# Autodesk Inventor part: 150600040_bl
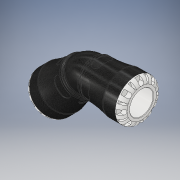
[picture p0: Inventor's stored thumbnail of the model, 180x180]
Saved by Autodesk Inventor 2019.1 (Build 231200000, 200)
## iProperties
Created: 2016-12
Part Number: 150600040_bl
Material: PVC-Piping
Description: PLASSON G-PLASS 45°  ELBOW 40-40
Document SubType Name: Modeling
Designer: KIM
Mass: 664.223 g
Surface Area: 733.008 cm^2
Volume: 474.445 cm^3
Density: 1.4 g/cm^3
Appearance: Black Cast
Author: KIM
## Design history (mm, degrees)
derived "150600.ipt"
feature "Solid1::150600.ipt" dims "ScaleForDerivedMember" = 10
tag "TaggingFeature1"
body "Solid1"
other parameters: "d1" = 31.08 [user parameter], "d8" = 59.5 [user parameter], "d13" = 8 [user parameter], "d14" = 8 [user parameter], "d15" = 0 [user parameter], "d17" = 360 deg [user parameter], "d19" = 8 deg [user parameter], "d20" = 0.8 [user parameter], "d21" = 0.8 [user parameter], "d22" = 8 deg [user parameter], "d24" = 0 [user parameter], "d26" = 360 deg [user parameter], "d33" = 7 [user parameter], "d43" = 54.6 [user parameter], "d51" = 0.7 [user parameter], "d54" = 14 [user parameter], "d55" = 8.8 [user parameter], "d57" = 15.68 [user parameter], "d58" = 0 [user parameter], "d74" = 0 [user parameter], "d77" = 3.33333 [user parameter], "d78" = 74 [user parameter], "d82" = 0.8 [user parameter], "d115" = 360 deg [user parameter], "d207" = 90 deg [user parameter], "d228" = 11.9 [user parameter], "d247" = 1.4 [user parameter], "d248" = 4.44 [user parameter], "d268" = 12.495 [user parameter], "d269" = 3.7485 [user parameter], "d270" = 91 [user parameter], "d277" = 135 deg [user parameter], "d279" = 3.7485 [user parameter], "d280" = 135 deg [user parameter], "d281" = 0 [user parameter], "d282" = 0 [user parameter], "l_" = 74 [user parameter], "A_" = 91 [user parameter]
